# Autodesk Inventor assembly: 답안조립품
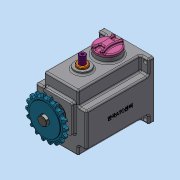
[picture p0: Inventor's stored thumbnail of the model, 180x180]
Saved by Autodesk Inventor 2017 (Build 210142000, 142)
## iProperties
Part Number: 답안조립품
Material: 일반
Document SubType Name: Assembly
Designer: MRC
Author: MRC
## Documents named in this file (16)
- C:\Users\MRC\Desktop\720212V1009\답안조립품.iam
- C:\Users\MRC\Desktop\720212V1009\본체.ipt
- C:\Users\MRC\Desktop\720212V1009\멈춤나사 M3.ipt
- C:\Users\MRC\Desktop\720212V1009\메인 축.ipt
- C:\Users\MRC\Desktop\720212V1009\베어링 608.ipt
- C:\Users\MRC\Desktop\720212V1009\베어링 6003.ipt
- C:\Users\MRC\Desktop\720212V1009\볼트 M4 x 10.ipt
- C:\Users\MRC\Desktop\720212V1009\부시.ipt
- C:\Users\MRC\Desktop\720212V1009\상부 캡.ipt
- C:\Users\MRC\Desktop\720212V1009\서브 축.ipt
- C:\Users\MRC\Desktop\720212V1009\스프로킷.ipt
- C:\Users\MRC\Desktop\720212V1009\슬라이더.ipt
- C:\Users\MRC\Desktop\720212V1009\오일 실 8 x 22 x 7.ipt
- C:\Users\MRC\Desktop\720212V1009\오일 실 17 x 32 x 8.ipt
- C:\Users\MRC\Desktop\720212V1009\커버.ipt
- C:\Users\MRC\Desktop\720212V1009\키 5 x 5.ipt
